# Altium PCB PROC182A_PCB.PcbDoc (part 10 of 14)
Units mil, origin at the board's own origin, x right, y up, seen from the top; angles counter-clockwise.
Board outline 3168.31 x 3700.79 mil, 8 copper layers (Top Layer, L2_GND1, L3_SIG1, L4_PWR1, L5_PWR2, L6_SIG2, L7_GND2, Bottom Layer), stack 58.1 mil thick; 580 components, 391 nets, 8314 pads, 4370 vias.
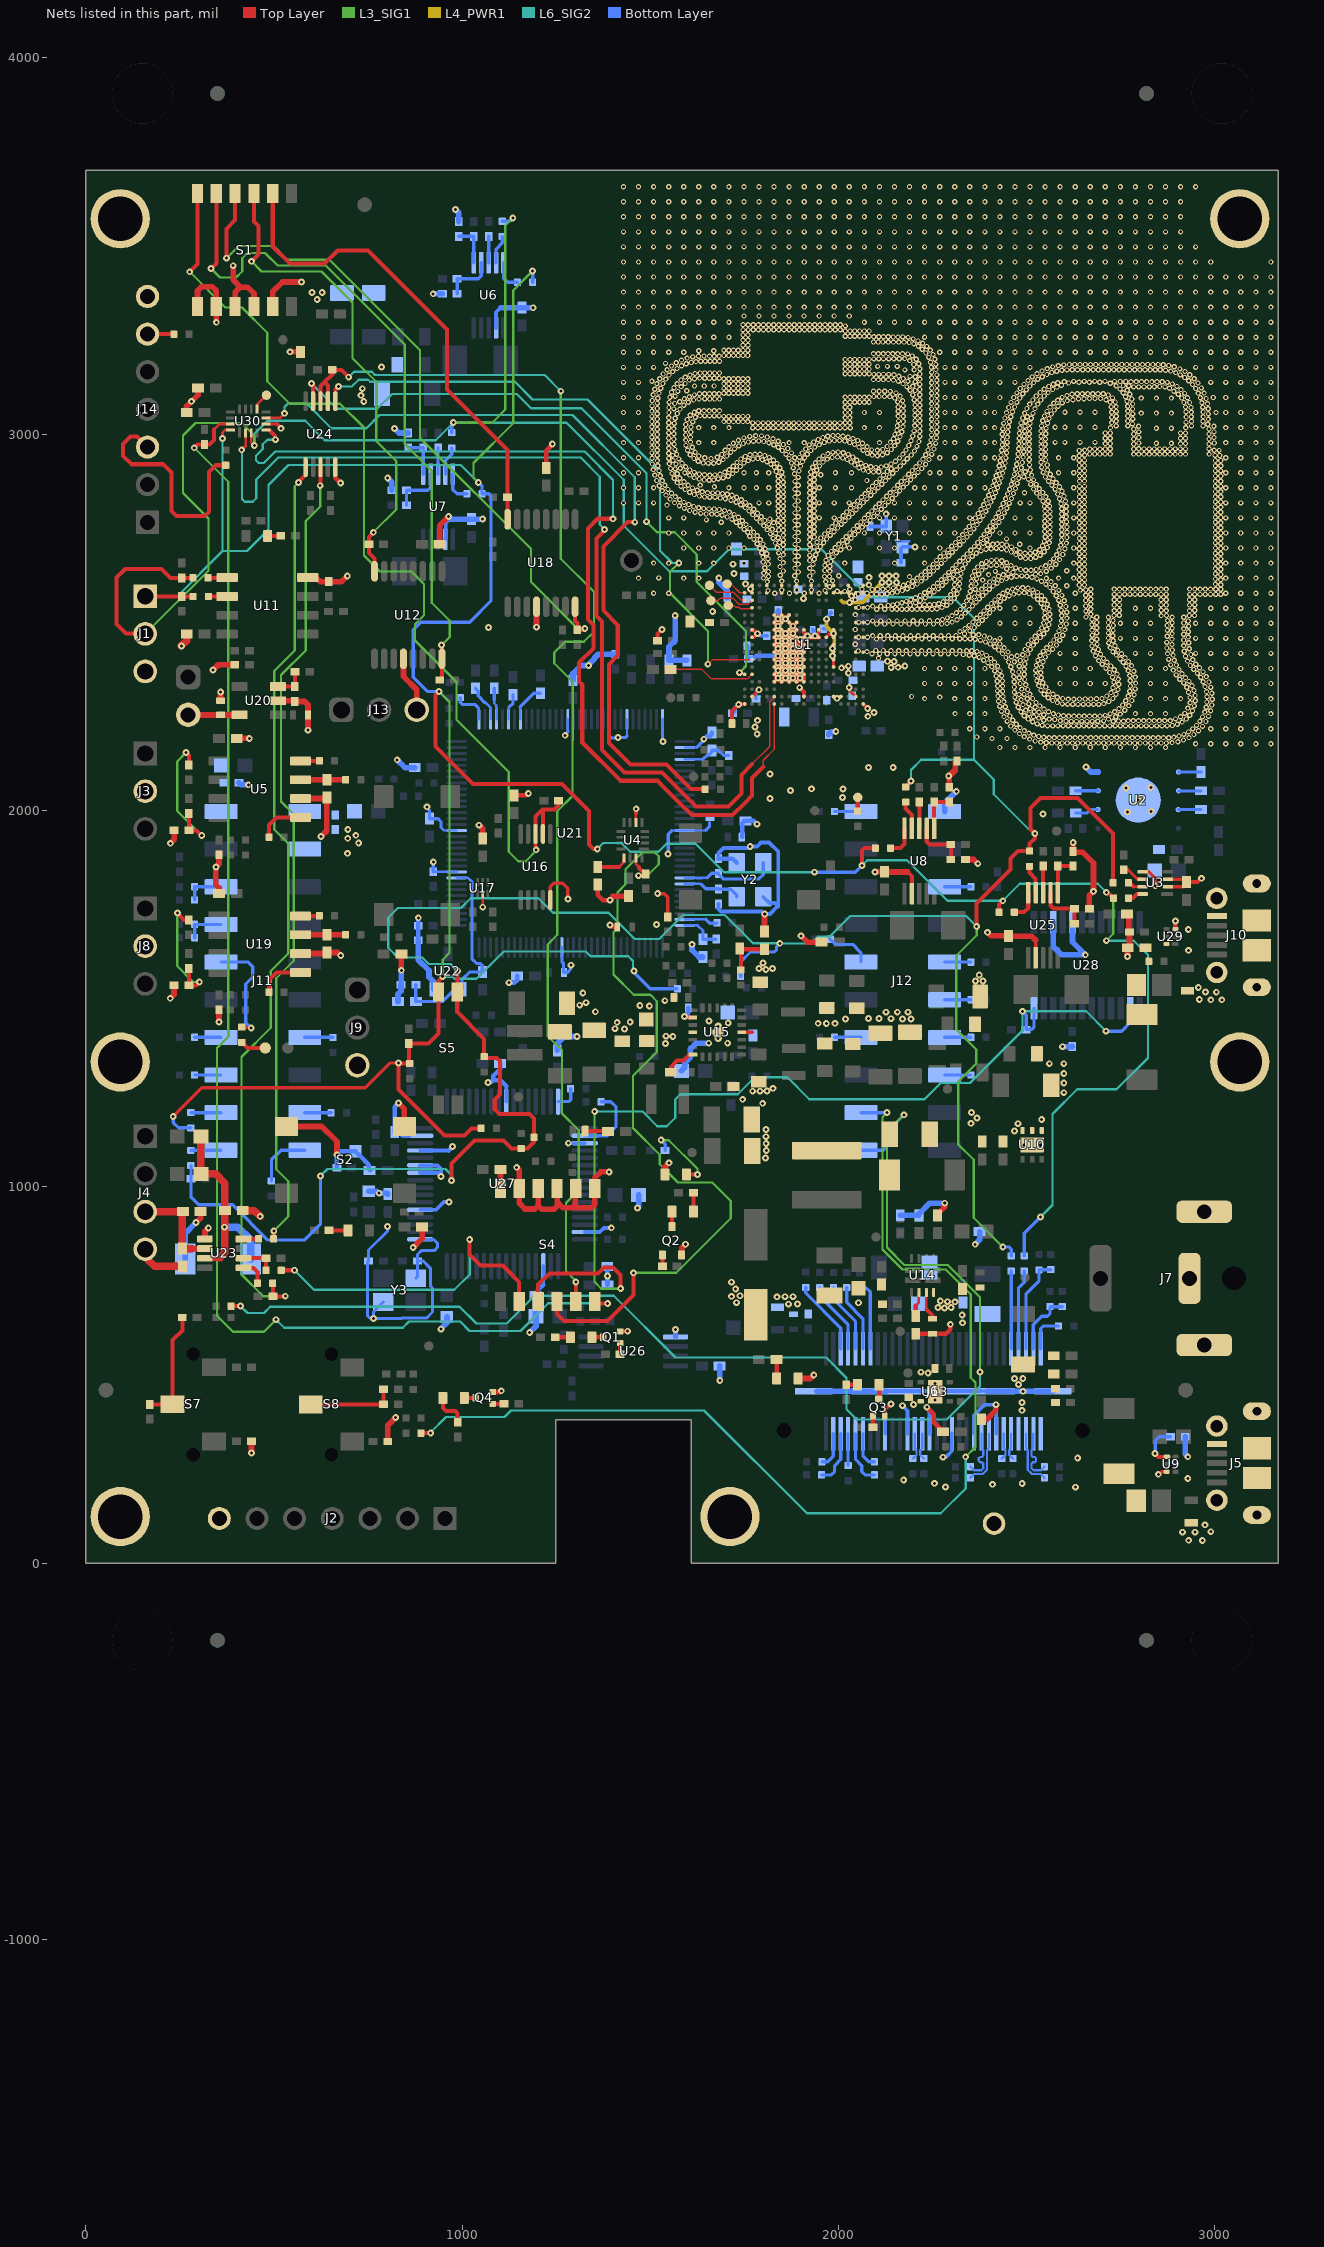
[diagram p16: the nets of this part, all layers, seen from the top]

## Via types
v1: diameter 13.77, hole 7, Top Layer to L2_GND1, tented both sides, 3444 vias
v2: diameter 18, hole 8, Top Layer to Bottom Layer, tented both sides, 911 vias
v3: diameter 13.77, hole 7, Top Layer to L2_GND1, tented top, 9 vias
v4: diameter 19.68, hole 7.87, Top Layer to Bottom Layer, 4 vias
v5: diameter 19.68, hole 7.87, Top Layer to Bottom Layer, tented both sides, 2 vias

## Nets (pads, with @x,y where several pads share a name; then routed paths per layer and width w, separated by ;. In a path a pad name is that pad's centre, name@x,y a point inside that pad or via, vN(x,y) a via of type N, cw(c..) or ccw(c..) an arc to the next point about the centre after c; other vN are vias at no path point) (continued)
GND: (continued)
  other v1: 2004.9,3290.63 1428.72,3297.48 1468.72,3297.48 1508.72,3297.48 1548.72,3297.48 1588.72,3297.48 1628.72,3297.48 1668.72,3297.48 1708.72,3297.48 2068.72,3297.48 2108.72,3297.48 2148.72,3297.48 2188.72,3297.48 2228.72,3297.48 2268.72,3297.48 2308.72,3297.48 2348.72,3297.48 2388.72,3297.48 2428.72,3297.48 2468.72,3297.48 2508.72,3297.48 2548.72,3297.48 2588.72,3297.48 2628.72,3297.48 2668.72,3297.48 2708.72,3297.48 2748.72,3297.48 2788.72,3297.48 2828.72,3297.48 2868.72,3297.48 2908.72,3297.48 2948.72,3297.48 2988.72,3297.48 3028.72,3297.48 3068.72,3297.48 3108.72,3297.48 3148.72,3297.48 1748.72,3314.06 1788.72,3314.06 1828.72,3314.06 1868.38,3314.06 1908.38,3314.06 1948.38,3314.06 1988.38,3314.06 2028.38,3314.06 1428.72,3337.48 1468.72,3337.48 1508.72,3337.48 1548.72,3337.48 1588.72,3337.48 1628.72,3337.48 1668.72,3337.48 1708.72,3337.48 1748.72,3337.48 1788.72,3337.48 1828.72,3337.48 1868.72,3337.48 1908.72,3337.48 1948.72,3337.48 1988.72,3337.48 2028.72,3337.48 2068.72,3337.48 2108.72,3337.48 2148.72,3337.48 2188.72,3337.48 2228.72,3337.48 2268.72,3337.48 2308.72,3337.48 2348.72,3337.48 2388.72,3337.48 2428.72,3337.48 2468.72,3337.48 2508.72,3337.48 2548.72,3337.48 2588.72,3337.48 2628.72,3337.48 2668.72,3337.48 2708.72,3337.48 2748.72,3337.48 2788.72,3337.48 2828.72,3337.48 2868.72,3337.48 2908.72,3337.48 2948.72,3337.48 2988.72,3337.48 3028.72,3337.48 3068.72,3337.48 3108.72,3337.48 3148.72,3337.48 1428.72,3377.48 1468.72,3377.48 1508.72,3377.48 1548.72,3377.48 1588.72,3377.48 1628.72,3377.48 1668.72,3377.48 1708.72,3377.48 1748.72,3377.48 1788.72,3377.48 1828.72,3377.48 1868.72,3377.48 1908.72,3377.48 1948.72,3377.48 1988.72,3377.48 2028.72,3377.48 2068.72,3377.48 2108.72,3377.48 2148.72,3377.48 2188.72,3377.48 2228.72,3377.48 2268.72,3377.48 2308.72,3377.48 2348.72,3377.48 2388.72,3377.48 2428.72,3377.48 2468.72,3377.48 2508.72,3377.48 2548.72,3377.48 2588.72,3377.48 2628.72,3377.48 2668.72,3377.48 2708.72,3377.48 2748.72,3377.48 2788.72,3377.48 2828.72,3377.48 2868.72,3377.48 2908.72,3377.48 2948.72,3377.48 2988.72,3377.48 3028.72,3377.48 3068.72,3377.48 3108.72,3377.48 3148.72,3377.48 1428.72,3417.48 1468.72,3417.48 1508.72,3417.48 1548.72,3417.48 1588.72,3417.48 1628.72,3417.48 1668.72,3417.48 1708.72,3417.48 1748.72,3417.48 1788.72,3417.48 1828.72,3417.48 1868.72,3417.48 1908.72,3417.48 1948.72,3417.48 1988.72,3417.48 2028.72,3417.48 2068.72,3417.48 2108.72,3417.48 2148.72,3417.48 2188.72,3417.48 2228.72,3417.48 2268.72,3417.48 2308.72,3417.48 2348.72,3417.48 2388.72,3417.48 2428.72,3417.48 2468.72,3417.48 2508.72,3417.48 2548.72,3417.48 2588.72,3417.48 2628.72,3417.48 2668.72,3417.48 2708.72,3417.48 2748.72,3417.48 2788.72,3417.48 2828.72,3417.48 2868.72,3417.48 2908.72,3417.48 2948.72,3417.48 2988.72,3417.48 3028.72,3417.48 3068.72,3417.48 3108.72,3417.48 3148.72,3417.48 1428.72,3457.48 1468.72,3457.48 1508.72,3457.48 1548.72,3457.48 1588.72,3457.48 1628.72,3457.48 1668.72,3457.48 1708.72,3457.48 1748.72,3457.48 1788.72,3457.48 1828.72,3457.48 1868.72,3457.48 1908.72,3457.48 1948.72,3457.48 1988.72,3457.48 2028.72,3457.48 2068.72,3457.48 2108.72,3457.48 2148.72,3457.48 2188.72,3457.48 2228.72,3457.48 2268.72,3457.48 2308.72,3457.48 2348.72,3457.48 2388.72,3457.48 2428.72,3457.48 2468.72,3457.48 2508.72,3457.48 2548.72,3457.48 2588.72,3457.48 2628.72,3457.48 2668.72,3457.48 2708.72,3457.48 2748.72,3457.48 2788.72,3457.48 2828.72,3457.48 2868.72,3457.48 2908.72,3457.48 2948.72,3457.48 2988.72,3457.48 3148.72,3457.48 1428.72,3497.48 1468.72,3497.48 1508.72,3497.48 1548.72,3497.48 1588.72,3497.48 1628.72,3497.48 1668.72,3497.48 1708.72,3497.48 1748.72,3497.48 1788.72,3497.48 1828.72,3497.48 1868.72,3497.48 1908.72,3497.48 1948.72,3497.48 1988.72,3497.48 2028.72,3497.48 2068.72,3497.48 2108.72,3497.48 2148.72,3497.48 2188.72,3497.48 2228.72,3497.48 2268.72,3497.48 2308.72,3497.48 2348.72,3497.48 2388.72,3497.48 2428.72,3497.48 2468.72,3497.48 2508.72,3497.48 2548.72,3497.48 2588.72,3497.48 2628.72,3497.48 2668.72,3497.48 2708.72,3497.48 2748.72,3497.48 2788.72,3497.48 2828.72,3497.48 2868.72,3497.48 2908.72,3497.48 2948.72,3497.48 1428.72,3537.48 1468.72,3537.48 1508.72,3537.48 1548.72,3537.48 1588.72,3537.48 1628.72,3537.48 1668.72,3537.48 1708.72,3537.48 1748.72,3537.48 1788.72,3537.48 1828.72,3537.48 1868.72,3537.48 1908.72,3537.48 1948.72,3537.48 1988.72,3537.48 2028.72,3537.48 2068.72,3537.48 2108.72,3537.48 2148.72,3537.48 2188.72,3537.48 2228.72,3537.48 2268.72,3537.48 2308.72,3537.48 2348.72,3537.48 2388.72,3537.48 2428.72,3537.48 2468.72,3537.48 2508.72,3537.48 2548.72,3537.48 2588.72,3537.48 2628.72,3537.48 2668.72,3537.48 2708.72,3537.48 2748.72,3537.48 2788.72,3537.48 2828.72,3537.48 2868.72,3537.48 2908.72,3537.48 1428.72,3577.48 1468.72,3577.48 1508.72,3577.48 1548.72,3577.48 1588.72,3577.48 1628.72,3577.48 1668.72,3577.48 1708.72,3577.48 1748.72,3577.48 1788.72,3577.48 1828.72,3577.48 1868.72,3577.48 1908.72,3577.48 1948.72,3577.48 1988.72,3577.48 2028.72,3577.48 2068.72,3577.48 2108.72,3577.48 2148.72,3577.48 2188.72,3577.48 2228.72,3577.48 2268.72,3577.48 2308.72,3577.48 2348.72,3577.48 2388.72,3577.48 2428.72,3577.48 2468.72,3577.48 2508.72,3577.48 2548.72,3577.48 2588.72,3577.48 2628.72,3577.48 2668.72,3577.48 2708.72,3577.48 2748.72,3577.48 2788.72,3577.48 2828.72,3577.48 2868.72,3577.48 2908.72,3577.48 1428.72,3617.48 1468.72,3617.48 1508.72,3617.48 1548.72,3617.48 1588.72,3617.48 1628.72,3617.48 1668.72,3617.48 1708.72,3617.48 1748.72,3617.48 1788.72,3617.48 1828.72,3617.48 1868.72,3617.48 1908.72,3617.48 1948.72,3617.48 1988.72,3617.48 2028.72,3617.48 2068.72,3617.48 2108.72,3617.48 2148.72,3617.48 2188.72,3617.48 2228.72,3617.48 2268.72,3617.48 2308.72,3617.48 2348.72,3617.48 2388.72,3617.48 2428.72,3617.48 2468.72,3617.48 2508.72,3617.48 2548.72,3617.48 2588.72,3617.48 2628.72,3617.48 2668.72,3617.48 2708.72,3617.48 2748.72,3617.48 2788.72,3617.48 2828.72,3617.48 2868.72,3617.48 2908.72,3617.48 1428.72,3657.48 1468.72,3657.48 1508.72,3657.48 1548.72,3657.48 1588.72,3657.48 1628.72,3657.48 1668.72,3657.48 1708.72,3657.48 1748.72,3657.48 1788.72,3657.48 1828.72,3657.48 1868.72,3657.48 1908.72,3657.48 1948.72,3657.48 1988.72,3657.48 2028.72,3657.48 2068.72,3657.48 2108.72,3657.48 2148.72,3657.48 2188.72,3657.48 2228.72,3657.48 2268.72,3657.48 2308.72,3657.48 2348.72,3657.48 2388.72,3657.48 2428.72,3657.48 2468.72,3657.48 2508.72,3657.48 2548.72,3657.48 2588.72,3657.48 2628.72,3657.48 2668.72,3657.48 2708.72,3657.48 2748.72,3657.48 2788.72,3657.48 2828.72,3657.48 2868.72,3657.48 2908.72,3657.48 2948.72,3657.48
  other v2: 2930.14,61.29 2966.32,60.76 2913.5,82.95 2946.78,82.95 2989.09,84.24 2973.52,102.49 2284.41,202.64 2629.78,202.51 2408.71,210.01 2488.02,212.24 2254.92,212.6 2173.08,221.6 2927.8,225.73 2635.36,279.7 2487.66,406.67 2199.28,421.83 2487.66,427.69 2478.38,475.32 2467.41,491.46 2489.5,491.46 2238.1,505.9 2218.86,507.95 2329.22,639.12 2328.48,659.72 2281.72,678.28 2264.28,679.81 2299.45,680.1 1867.11,688.69 1890.71,689.21 1729.1,692.46 2052.8,692.41 2309.31,694.85 2289.77,695.33 2270.3,696.75 1836.28,708.23 1857.83,708.52 1879.37,708.52 1715.67,709.58 1738.51,711 1726.65,729.18 1715.43,746.93 1390.72,1039.43 1805.9,1077.2 1808.23,1096.81 974.7,1107.54 1807.94,1115.66 1807.34,1133.65 2467.62,1148.59 1807.04,1152.62 2476.71,1168.11 2352.07,1169.26 2539.87,1179.47 2367.71,1182.91 2353.19,1198.09 1798.48,1222.21 1745.26,1232.95 2598.37,1250.48 1772.04,1254.37 1791.58,1254.37 1809.93,1254.77 1825.57,1262.16 2598.37,1276.15 2598.37,1301.81 2560.02,1327.48 2598.37,1327.48 1540.24,1381.5 1705.5,1382.07 1559.8,1400.05 1541.63,1400.56 1431.32,1419.47 1405.91,1420.36 1945.86,1434.73 1967.57,1434.42 1990.66,1434.67 1706.91,1435.82 1411.86,1437.35 1446.64,1438.58 1655.61,1441.09 2018.24,1446.23 2170.18,1446.14 2192.27,1445.88 2139.59,1447.05 2079.52,1447.85 2107.85,1447.85 2125.82,1464.45 2156.25,1464.45 2184.79,1464.45 1353.91,1465.5 1497.32,1481.02 1472.05,1481.74 1312.4,1483.01 1329.15,1489.61 1538.6,1494.91 2989.13,1497.28 2958.54,1498.19 3018.33,1497.32 224.58,1501.17 1320.57,1515.23 2975.2,1517.88 3003.74,1517.55 2955.88,1530.2 2364.07,1547.42 2383.59,1547.42 2373.83,1562.93 1806.87,1577.89 1824.73,1580.18 1788.87,1580.62 1799.26,1595.32 2929.95,1628.72 2929.12,1684 1516.66,1697.15 695.14,1886.32 224.75,1912.88 725.14,1913.47 696.14,1926.32 717.5,1934.3 696.27,1949.79 2543.55,1990.67 2767.72,1996.06 2830.71,1998.03 2796.23,2027.59 1817.85,2031.89 2010.49,2034.35 1872.45,2053.61 2011.6,2057.18 1928.45,2057.65 2763.78,2060.04 2829.72,2061.02 1817.85,2097.47 2079.59,2114.28 2145.16,2114.28 1784.04,2203.37 1778.13,2221.64 1785.02,2239.9 2077.88,2250.39 2094.12,2260.51 1996.01,2298.17 2026.08,2365.54 2008.46,2379.38 2140.02,2380.38 2158.45,2380.58 2026.08,2383.59 2176.13,2384.41 2147.86,2396.26 2129.84,2396.68 1898.23,2454.32 1070.01,2486.68 1665.81,2528.52 1907.06,2562.86 2034.62,2570.67 1766.28,2588.28 2080.48,2599.8 1753.06,2602.44 2134.19,2605.63 2154.32,2605.63 2080.87,2619.66 2115.84,2623.61 2133.82,2623.61 2153.03,2623.61 1722.44,2629.92 1719.99,2654.51 677.27,2870.41 738.81,3086.68 731.44,3103.1 734.74,3120.8 785.86,3178.55 346.89,3297.26 615.09,3357.47 601.3,3376.39 628.2,3376.39
  other v3: 1688.23,2765.94 1648.86,2772.16 1544.19,2811.53 1670.21,2860.34 1632.73,2864.66 2762.29,3099.2 2592.19,3130.16 1504.08,3140.67 1540.2,3187.97
  other v4: 2256.79,434.09 2256.79,477.4 2492.67,1111.65 2535.97,1111.65
  other v5: 1680.35,1394.98 1680.35,1426.56
GPADC1: TP11.1 U1.T4 | length 68.3
  Top Layer w4: TP11.1@1707.08,2545.15 1708.53,2543.7 1723.27,2543.7 1725.16,2541.81 1727.14,2539.83 1736.2,2539.83 1740.03,2536 1765.64,2536 1768.7,2539.06 U1.T4@1770.28,2539.06
GPADC2: TP12.1 U1.T3 | length 123.8
  Top Layer w4: TP12.1@1660.83,2557.74 1679.14,2557.74 1686.05,2564.65 1719.46,2564.65 1736.28,2547.83 1759.42,2547.83 U1.T3@1770.28,2558.75 U1.T3@1770.28,2558.75
GPADC3: TP5.1 U1.U2 | length 56.3
  Top Layer w4: TP5.1@1703.94,2601.77 1714.1,2601.77 1737.43,2578.43 U1.U2@1750.59,2578.43
GPADC4: TP6.1 U1.U3 | length 110.2
  Top Layer w4: TP6.1@1657,2598.24 1675.51,2579.73 1720.99,2579.73 1741.63,2559.08 1741.63,2558.75 U1.U3@1750.59,2558.75
HARDWARE_TRIGGER: J15.2 R254.1 | length 68.5
  Top Layer w10.8: R254.1@414.56,1384.37 429.5,1369.43 J15.2@476.88,1369.43
HOST_CLK_REQ: TP4.1 U30.9 | length 47.5
  Top Layer w7: U30.9@455.49,3066.34 455.49,3078.91 TP4.1@480.15,3103.58
HOST_CLK_REQ_SPIB_MISO: R270.2 U30.7 | length 2199.3
  Top Layer w7: U30.7@479.37,3042.98 515.53,3042.98 v2@528.05,3055.49
  Top Layer w10.8: v2(1458.91,2766.17) 1439.56,2766.17 1375.46,2702.08 1375.46,2530.98 1413.41,2493.03 1413.41,2411.79 1390.21,2388.59 1390.21,2179.27 1446.75,2122.72 1542.66,2122.72 1608.63,2056.76 R270.2@1645.51,2056.76
  L6_SIG2 w6: v2(528.37,3055.49) 528.37,3072.44 538.54,3082.6 585.98,3082.6 652.63,3015.96 745.97,3015.96 780.65,3050.64 1293.48,3050.64 1458.91,2885.22 v2(1458.91,2766.17)
HOSTIRQ_FTDI_IN: R216.1 U27.32 | length 64.7
  Bottom Layer w8.7: U27.32@1255.02,1226.8 1282.95,1226.8 1288.3,1232.15 R216.1@1288.3,1261.32
HOSTIRQ_FTDI_OUT: R217.1 U27.34 | length 191
  Bottom Layer w8.7: U27.34@1325.89,1136.25 1384.95,1136.25 1408.77,1160.07 1408.77,1212.89 1395.24,1226.42 1369.11,1226.42 R217.1@1369.01,1226.32
I2C_SCL: J1.1 R25.2 R55.2 R60.1 R89.1 R96.2 R97.1 R108.2 R109.2 R137.2 R159.2 R164.1 R199.1 R224.1 S5.2 U30.16 | length 9572.2
  Top Layer w7: v2(363.51,2988.52) 363.51,3004.42 370.31,3011.22 U30.16@384.62,3011.22
  Top Layer w8.7: v2(232.5,1187.58) 308.85,1263.93 742.83,1263.93 808.09,1329.2 v2(830.69,1329.2)
  Top Layer w10.8: J1.1@158.07,2569.5 158.78,2568.79 R97.1@254.77,2568.79 R159.2@285.26,2568.79 ; R199.1@860.53,1327.87 R199.1@859.86,1328.54 ; v2(938.48,2316.6) 928.92,2307.04 928.92,2170.56 1028.72,2070.75 1264.77,2070.75 1337.1,1998.43 1337.1,1909.31 1348.71,1897.69 v2(1359.02,1897.69) ; v2(948.29,1558.77) 937.08,1547.56 S5.2@937.08,1518.36 937.08,1407.62 910.54,1381.09 R164.1@858.69,1381.09 858.69,1329.71 R199.1@859.86,1328.54 ; R96.2@1050.6,1155.7 1025.05,1155.7 1006.37,1137.02 953.19,1137.02 830.69,1259.52 v2(830.69,1329.2) 831.36,1328.54 R199.1@859.86,1328.54 ; v2(2062.31,1854.08) 2062.13,1854.26 2062.13,1894.02 2068.45,1900.35 R109.2@2097.68,1900.35 ; R137.2@2426.53,1730.11 2426.53,1750.41 v2(2436.39,1760.28) ; v2(2711.47,1782.77) 2712.85,1781.39 2716.26,1781.39 2725.86,1771.78 2726.36,1771.78 2730.1,1768.04 R55.2@2730.1,1767.55
  L3_SIG1 w6: v2(938.48,2316.6) 966.35,2288.73 966.35,1622.03 948.29,1603.97 v2(948.29,1558.77) ; v2(1043.12,2871.78) 1030.28,2884.62 1030.28,2923.5 1135.53,3028.75 1135.53,3381.91 v2(1187.17,3433.55) ; v2(2711.38,1654.24) 2729.65,1672.51 2729.65,1764.59 v2(2711.47,1782.77)
  L6_SIG2 w6: J1.1@158.07,2569.5 243.71,2569.5 363.51,2689.3 ; v2(363.51,2988.52) 363.51,2689.3 ; v2(948.29,1558.77) 974.25,1558.77 980.05,1552.96 1038.26,1552.96 1110.91,1625.61 1328.48,1625.61 1341.13,1612.96 1441.3,1612.96 1453.95,1600.31 1453.95,1582.22 1454.17,1582.01 1454.17,1576.18 v2(1456.46,1573.88) ; v2(1043.12,2871.78) 996.65,2918.26 538.94,2918.26 485.86,2865.17 485.86,2746.67 428.49,2689.3 363.51,2689.3 ; v2(1359.02,1897.69) 1375.12,1913.8 1423.52,1913.8 1446.68,1890.64 1521.97,1890.64 1543.01,1911.68 1620.14,1911.68 1695.54,1836.28 v2(1936.42,1836.28) ; v2(2062.31,1854.08) 2076.06,1867.83 2181.8,1867.83 2289.36,1760.28 v2(2436.39,1760.28) 2481.61,1805.49 2688.75,1805.49 v2(2711.47,1782.77) ; v2(2536.34,920.08) 2568.55,952.28 2568.55,1193.69 2634.25,1259.39 2738.8,1259.39 2822.06,1342.65 2822.06,1616.65 2784.47,1654.24 v2(2711.38,1654.24)
  Bottom Layer w8.7: v2(232.5,1187.58) 232.5,1171.05 246.45,1157.1 R224.1@279.56,1157.1 ; v2(938.48,2316.6) 907.72,2316.6 869.93,2354.39 869.93,2480.45 889.98,2500.5 1020.38,2500.5 1076.73,2556.85 1076.73,2836.52 1071.63,2841.61 R108.2@1052.99,2841.61 1052.99,2861.91 v2(1043.12,2871.78) ; v2(1187.17,3433.55) 1187.28,3433.44 1187.28,3403.51 R25.2@1187.39,3403.4 ; v2(1456.46,1573.88) 1456.46,1571.36 1459.38,1568.44 1459.38,1567.07 1499.48,1526.97 R89.1@1571.15,1526.97 ; v2(1936.42,1836.28) 2044.51,1836.28 v2(2062.31,1854.08) ; R60.1@2493.18,817.03 2493.18,876.92 v2(2536.34,920.08)
I2C_SCL_SPIB_CLK: U1.N16 U30.2 | length 2720.3
  Top Layer w4: 1770.34,2123.54 1817.92,2171.11 1817.92,2290.47 1829.33,2301.89 U1.N16@1829.33,2302.84
  Top Layer w7: v2(414.51,2958.37) 415.34,2958.37 424.94,2967.97 424.94,2991.59 424.43,2992.11 424.43,3002.91 U30.2@423.99,3003.35
  Top Layer w10.8: v2(1378.46,2746.54) 1378.46,2744.63 1356.44,2722.61 1356.44,2516.54 1371.19,2501.79 1371.19,2161.52 1431.85,2100.86 1531.2,2100.86 1613.27,2018.79 1620.75,2011.31 1708.01,2011.31 1715.5,2018.79 1741.88,2045.18 1741.88,2095.08 1770.34,2123.54
  L6_SIG2 w6: v2(414.51,2958.37) 415.47,2957.41 415.47,2827.5 422.61,2820.36 443.69,2820.36 453.3,2829.96 453.3,2879.6 511.43,2937.73 1315.15,2937.73 1365.95,2886.92 1365.95,2760 1378.46,2747.5 v2(1378.46,2746.54)
I2C_SDA: J1.2 R29.2 R56.2 R59.1 R90.1 R98.1 R100.2 R102.2 R110.2 R111.2 R139.2 R160.2 R166.1 R197.1 R238.1 S5.1 U30.3 | length 11184.4
  Top Layer w7: U30.3@439.74,3003.35 439.74,2977.98 447.79,2969.93 v2(447.79,2969.77)
  Top Layer w10.8: J1.2@158.07,2469.5 157.57,2470 107.1,2470 81.89,2495.21 81.89,2619.19 105.04,2642.34 200.72,2642.34 224.73,2618.33 R98.1@254.77,2618.33 R160.2@284.77,2618.33 ; v2(971.74,1017.32) 971.74,1061.84 1033.26,1123.36 1109.38,1123.36 1130.7,1102.04 1174.15,1102.04 1190.95,1118.84 1190.95,1182.32 1179.53,1193.74 1098.7,1193.74 1086.75,1205.69 1086.75,1232.31 1100.23,1245.8 1100.23,1334.11 1091.47,1342.88 1061.61,1342.88 R197.1@1058.48,1346.02 1058.48,1392.92 987.08,1464.32 S5.1@987.08,1518.36 987.55,1518.83 987.55,1573.01 v2(988.02,1573.48) ; R111.2@2178.41,2062.59 2178.9,2062.59 2182.85,2066.54 2182.85,2068.83 v2(2192.81,2078.79) ; v2(2366.94,1691.84) 2366.94,1752.67 2457.26,1842.99 2457.26,1872.23 2477.38,1892.35 R139.2@2507.26,1892.35 2507.26,1912.22 2521.42,1926.39 v2(2521.42,1939.35) 2510.42,1950.36 2510.42,2006.87 2536.94,2033.39 2635.26,2033.39 2727.71,1940.95 2727.71,1940.71 2729.7,1938.72 R56.2@2729.7,1807.94
  L3_SIG1 w6: J1.2@158.07,2469.5 325.91,2637.35 325.91,2776.12 258.27,2843.76 258.27,2996.46 291.34,3029.53 414.8,3029.53 447.79,2996.54 v2(447.79,2969.77) ; v2(976.44,3030.64) 1079.85,3030.64 1114.77,3065.56 1114.77,3554.37 v2(1134.77,3574.37) ; v2(2366.94,1691.84) 2366.94,1668.6 2312.88,1614.53 2312.88,1418.63 2366.17,1365.33 2366.17,1328.1 2318.31,1280.24 2318.31,1112.68 2358.93,1072.06 2358.93,918.17 v2(2436.34,840.76)
  L6_SIG2 w6: v2(447.79,2969.77) 447.79,3000.4 482.89,3035.49 583,3035.49 634.6,2983.9 929.7,2983.9 v2(976.44,3030.64) 1277.6,3030.64 1429.06,2879.18 1429.06,2756.6 1550.13,2635.52 1650.74,2635.52 1709.31,2694.09 1954.84,2694.09 2082.28,2566.64 2304.18,2566.64 2359.91,2510.91 2359.91,2134.78 ; v2(623.98,1029.47) 642.33,1047.82 955.93,1047.82 971.74,1032.01 v2(971.74,1017.32) ; v2(988.02,1573.48) 968.92,1592.58 911.57,1592.58 894.24,1609.9 829.52,1609.9 803.96,1635.46 803.96,1716.16 829.21,1741.42 996.99,1741.42 1022.63,1767.06 1202.92,1767.06 1241.5,1728.47 1388.85,1728.47 1458.33,1658.99 1523.97,1658.99 1587.69,1722.71 1697.45,1722.71 1772.84,1647.32 v2(1843.91,1647.32) ; v2@1843.91,1647.13 1927.53,1647.13 1945.37,1664.97 1976.08,1664.97 2030.9,1719.78 2339,1719.78 v2(2366.94,1691.84) ; v2(2192.81,2078.79) 2192.81,2107.96 2219.63,2134.78 2359.91,2134.78 ; v2(2521.42,1939.35) 2509.17,1951.6 2503.98,1951.6 2412.16,2043.42 2412.16,2082.53 2359.91,2134.78
  Bottom Layer w8.7: R238.1@279.56,1057.1 R166.1@279.56,1022.1 279.56,973.74 300.6,952.7 390.37,952.7 484.08,858.99 581.05,858.99 623.98,901.92 v2(623.98,1029.47) ; R110.2@972.26,3003.85 972.26,3026.46 v2(976.44,3030.64) ; R29.2@1106.66,3565.64 1126.05,3565.64 v2(1134.77,3574.37) ; R90.1@1740.13,1560.01 1740.13,1598.18 1766.15,1624.2 1828.79,1624.2 1835.39,1630.81 1835.39,1638.81 v2(1843.91,1647.32) ; v2(2436.34,840.76) 2451.86,840.76 2458.51,834.11 R59.1@2458.51,817.03
I2C_SDA_SPIB_MOSI: U1.N17 U30.5 | length 2720.4
  Top Layer w4: 1799.93,2115.55 1799.93,2133.6 1829.59,2163.25 U1.N17@1829.59,2282.9
  Top Layer w7: U30.5@479.11,3011.22 U30.5@487.96,3011.22
  Top Layer w10.8: U30.5@487.96,3011.22 496.86,3002.32 496.86,3001.77 503.04,2995.59 503.04,2986.77 v2(504.42,2985.39) ; v2(1400.59,2775.24) 1359.53,2775.24 1333.88,2749.6 1333.88,2507.59 1348.63,2492.85 1348.63,2430.31 1311.06,2392.75 1311.06,2342.93 1319.11,2334.88 1319.11,2181.23 1421.08,2079.26 1518.91,2079.26 1528.36,2069.82 1579.38,2018.79 1610.53,1987.65 1718.51,1987.65 1749.65,2018.79 1770.26,2039.4 1770.26,2085.88 1799.93,2115.55
  L6_SIG2 w6: v2(504.42,2985.39) 482.96,2985.39 470.43,2972.86 470.43,2960.71 452.07,2942.35 452.07,2930.97 459.79,2923.25 473.27,2923.25 503.67,2953.64 1325.47,2953.64 1400.59,2878.53 v2(1400.59,2775.24)
JTAG_TDO: R93.2 U1.T13 | length 231.1
  Top Layer w4: R93.2@1554,2374.99 1637.11,2374.99 1661.57,2350.53 1758.91,2350.53 U1.T13@1770.28,2361.9
LIN_BUS: C132.1 J4.3 R21.1 U23.6 | length 258.7
  Top Layer w15: 281.35,836.32 U23.6@316.77,836.32
  Top Layer w20: J4.3@158.07,934.5 R21.1@258.07,934.5 256.77,933.21 C132.1@256.77,836.32 281.35,836.32
LIN_PHY_EN: R17.1 R88.2 U23.2 | length 92
  Top Layer w10.8: U23.2@419.13,810.73 R17.1@479.13,810.73 R88.2@479.13,778.73
LIN_PHY_EN_CTRL: R88.1 S4.2 | length 884
  Top Layer w10.8: R88.1@520.19,779.02 520.47,778.74 v2(554.35,778.75) ; v2(1020.01,860.48) 1020.01,820.44 1049.37,791.09 1107.92,791.09 1151.62,747.39 S4.2@1151.62,696.54
  L6_SIG2 w6: v2(554.35,778.75) 606.4,726.71 978.95,726.71 1020.01,767.77 v2(1020.01,860.48)
LIN_PHY_RX: R18.1 R22.1 U24.1 | length 2454.8
  Top Layer w10.8: R18.1@497.04,743.84 R22.1@497.04,709.34 529.91,709.34 v2(530.38,709.81) ; v2(565.44,2871.3) 565.44,2872.76 583.97,2891.29 583.97,2911.91 U24.1@584.32,2912.26
  L3_SIG1 w6: v2(530.38,709.81) 471.6,709.81 413.71,767.7 413.71,1345.48 491.49,1423.26 491.49,1573.93 538.09,1620.53 538.09,1912.71 500.87,1949.93 500.87,2370.63 555.64,2425.4 555.64,2861.51 v2(565.44,2871.3)
LIN_PHY_RX_UARTB_TX: U1.U13 U24.9 | length 1759.4
  Top Layer w4: v2(1737.01,2366.36) 1740.8,2366.36 1744.14,2363.02 1749.48,2363.02 U1.U13@1750.59,2361.9
  Top Layer w10.8: v2(599.79,3134.61) 604.01,3130.39 U24.9@604.01,3087.46
  L3_SIG1 w6: v2(1489.78,2767.46) 1517.96,2739.28 1564.67,2739.28 1623.51,2680.44 1623.51,2660.18 1623.51,2607.25 1754.08,2476.68 1754.08,2383.43 v2(1737.01,2366.36)
  L6_SIG2 w6: v2(599.79,3134.61) 666.84,3067.55 774.81,3067.55 814.17,3106.92 1144.78,3106.92 1182.67,3069.03 1316.86,3069.03 1489.78,2896.11 v2(1489.78,2767.46)
LIN_PHY_TX: R19.1 U24.3 | length 2155.7
  Top Layer w10.8: R19.1@499.49,861.92 499.49,882.7 v2(499.67,882.88) ; v2(623.03,2863.19) 623.5,2863.66 623.5,2912.07 U24.3@623.69,2912.26
  L3_SIG1 w6: v2(499.67,882.88) 538.03,921.25 538.03,1015.49 506.37,1047.15 506.37,1554.57 552.5,1600.69 552.5,1990.34 519.08,2023.75 519.08,2360.09 584.43,2425.43 584.43,2769.33 623.03,2807.94 v2(623.03,2863.19)
LIN_PHY_TX_UARTB_RX: U1.T11 U24.6 | length 1721.8
  Top Layer w4: v2(1652.72,2388.94) 1665.09,2401.27 U1.T11@1770.28,2401.27
  Top Layer w10.8: U24.6@663.06,3087.46 663.06,3118.19 v2(671.23,3126.35)
  L3_SIG1 w6: v2(1575.57,2657.88) 1552.03,2634.34 1552.03,2577.69 1653.07,2476.65 1653.07,2389.29 v2(1652.72,2388.94)
  L6_SIG2 w6: v2(671.23,3126.35) 706.79,3126.35 725.28,3144.85 750.22,3144.85 756.15,3138.92 1140.24,3138.92 1187.22,3091.94 1333.37,3091.94 1525.65,2899.66 1525.65,2690.58 1556.05,2660.18 1558.34,2657.88 v2(1575.57,2657.88)
LIN_VDD: C123.1 D8.2 R31.2 R32.2 U23.7 | length 552.5
  Top Layer w15: U23.7@316.77,810.73 355.67,810.73 356.73,811.79
  Top Layer w20: R31.2@306.06,1134.5 R32.2@306.06,1034.5 345.85,1034.5 369.9,1010.45 C123.1@369.9,937.13 369.9,824.97 356.73,811.79
  Bottom Layer w20: v2(369.03,893.27) 404.26,893.27 437.98,859.56 D8.2@437.98,808.26
LVDS_VALID: R257.2 TP3.1 | length 36.5
  Top Layer w10.8: R257.2@2051.07,1998.65 TP3.1@2051.07,2035.16
MCU_3V3: C119.1 J11.1 R154.1
MCU_5V: C120.1 J11.2 R155.1
MCU_SOP0: J12.19 R235.2 | length 3360.2
  Top Layer w10.8: R235.2@386.3,683.31 386.42,683.19 411.18,683.19 v2(411.42,683.43)
  L3_SIG1 w6: v2(2173.96,1191.67) 2128.66,1146.37 2128.66,838.95 2174.68,792.93 2289.83,792.93 2375.55,707.21 v2(2375.55,508.76)
  L6_SIG2 w6: v2(411.42,683.43) 429.67,665.18 473.71,665.18 490.51,681.98 993.29,681.98 1037.99,637.28 1118.7,637.28 1192.19,710.76 1402.67,710.76 1566.57,546.87 1967.05,546.87 2021.2,492.73 2021.2,409.77 2048.65,382.32 2287.42,382.32 2375.55,470.45 v2(2375.55,508.76)
  Bottom Layer w8.7: J12.19@2059.56,1097.45 2119.12,1097.45 2144.28,1122.61 2144.28,1161.99 v2(2173.96,1191.67)
MCU_SOP1: J12.17 R244.2 | length 2866.7
  Top Layer w10.8: R244.2@891.14,346.19 891.3,346.35 916.34,346.35 v2(916.5,346.51)
  L3_SIG1 w6: v2(2129.09,1197.52) 2116.66,1185.1 2116.66,833.98 2169.71,780.93 2284.54,780.93 2351.42,714.06 2351.42,492.91 2363.73,480.59 2363.73,309.14 v2(2337.76,283.17)
  L6_SIG2 w6: v2(916.5,346.51) 916.5,348.18 957.38,389.06 1112.44,389.06 1129.76,406.38 1642.83,406.38 1916.2,133.02 2271.8,133.02 2337.76,198.98 v2(2337.76,283.17)
  Bottom Layer w8.7: J12.17@2059.56,1197.45 2059.63,1197.52 v2(2129.09,1197.52)
MUX_CTRL_FTDI_DCA_LP_UARTA: R95.1 S1.6 U16.7 U16.8 | length 2619.1
  Top Layer w8: 1214.07,2002.98 1214.65,2002.4
  Top Layer w10.8: v2(276.25,3431.28) 296.89,3451.92 S1.6@296.89,3639.18 ; v2(1196.88,1895.79) 1196.88,1897.74 1194.68,1899.94 1194.68,1916.18 1194.77,1916.27 1194.77,1937.66 U16.8@1194.96,1937.85 1194.96,1983.88 1214.07,2002.98 ; U16.7@1214.65,1937.85 1214.65,2002.4 1245.08,2002.4 1256.51,2013.83 R95.1@1256.51,2026.17
  L3_SIG1 w6: v2(276.25,3431.28) 370.92,3336.62 415.35,3336.62 482.28,3269.69 482.28,3140.75 542.32,3080.71 675.81,3080.71 739.02,3017.49 739.02,2677.32 781.5,2634.84 865.59,2634.84 898.92,2601.52 898.92,2519.11 874.81,2495 874.81,2451.54 985.01,2341.34 985.01,2241.48 1124.01,2102.48 1124.01,1890.75 1149.2,1865.56 1168.77,1865.56 1196.88,1893.67 v2(1196.88,1895.79)
MUX_CTRL_FTDI_DCA_RS232: R7.1 S1.3 U12.16 | length 1305.3
  Top Layer w10.8: v2(440.39,3459.09) 459.22,3477.92 459.22,3552.37 446.89,3564.71 S1.3@446.89,3639.18 ; v2(764.13,2739.16) 752.22,2727.24 752.22,2684.8 767.33,2669.7 U12.16@767.33,2635.52
  L3_SIG1 w6: v2(440.39,3459.09) 467.12,3432.35 626.17,3432.35 708.66,3349.86 708.66,3201.77 771.54,3138.89 771.54,2981.62 824.8,2928.36 824.8,2799.83 v2(764.13,2739.16)
MUX_CTRL_FTDI_DCA_SPIA: R12.2 S4.3 U28.14 U28.24 | length 2723.4
  Top Layer w10.8: S4.3@1202.05,696.11 1202.05,740.63 1231.65,770.23 1361.2,770.23 1376.93,785.96 1401.23,785.96 1421.24,765.95 v2(1421.24,729.92)
  L3_SIG1 w6: v2@1351.9,1199.97 1351.9,747.96 1369.94,729.92 v2(1421.24,729.92)
  L6_SIG2 w6: v2(1352.16,1200.23) 1479.62,1200.23 1518.57,1161.28 1543.42,1161.28 1566.05,1183.91 1566.05,1232.5 1579.77,1246.22 1732.44,1246.22 1777.49,1291.28 1864.37,1291.28 1922.38,1233.27 2228.45,1233.27 2271.53,1276.34 2349.34,1276.34 2488.6,1415.6 v2(2488.6,1466.56) 2657.86,1466.56 v2(2710.63,1413.79)
  Bottom Layer w8.7: v2(2488.6,1466.56) 2498.56,1456.6 R12.2@2498.56,1418.15 2512.87,1418.15 2519.18,1424.47 U28.24@2519.18,1475.05 ; v2(2710.63,1413.79) 2751.87,1413.77 2775.09,1436.99 U28.14@2775.09,1475.05
MUX_CTRL_LIN_UARTB: R253.1 S4.5 U24.7 U24.8 | length 3427.4
  Top Layer w10.8: U24.8@623.69,3087.46 623.69,3127.27 634.79,3138.37 ; U24.7@643.38,3087.46 643.38,3129.78 634.79,3138.37 ; v2(698.52,3151.47) 678.97,3171.01 R253.1@655.04,3171.01 655.04,3158.63 634.79,3138.37 ; S4.5@1302.05,696.11 v2(1302.02,747.83)
  L3_SIG1 w6: v2(1262.13,3114.05) 1262.13,2669.17 1350.04,2581.26 1350.04,2475.2 1323.45,2448.61 1273.39,2448.61 1244.92,2420.14 1244.92,2391.49 1293.89,2342.51 1293.89,2185.83 1293.42,2185.35 1293.42,2038.85 1252.87,1998.3 1252.87,1669.8 1227.27,1644.2 1227.27,1400.69 1265.06,1362.9 1265.06,1195.36 1310.04,1150.38 1310.04,991.05 1276.15,957.16 1276.15,775.77 1302.02,749.9 v2(1302.02,747.83)
  L6_SIG2 w6: v2(698.52,3151.47) 712.5,3165.45 759.99,3165.45 768.48,3156.96 1219.22,3156.96 v2(1262.13,3114.05)
MUX_CTRL_SPIB_I2C_SYS_RST_HOST_CLK_REQ: R271.1 S4.6 U30.15 | length 3656.1
  Top Layer w7: 340.85,3012.15 355.67,3026.97 U30.15@384.62,3026.97
  Top Layer w10.8: v2(288.35,2963.63) 297.44,2972.73 329.29,2972.73 340.85,2984.29 340.85,3012.15 ; S4.6@1352.05,696.11 1357.39,690.76 v2(1386.8,690.76)
  L3_SIG1 w6: v2(288.35,2963.63) 378.45,2873.53 378.45,1398.43 349.03,1369.01 349.03,657.89 391.49,615.44 473.86,615.44 v2(505.76,647.34)
  L6_SIG2 w6: v2(505.76,647.34) 527.14,625.95 842.08,625.95 858.6,642.47 994.75,642.47 1019.81,617.41 1155.4,617.41 1228.75,690.76 v2(1386.8,690.76)
MUX_CTRL_UARTA_CAN_FD: R128.1 S1.4 U18.8 | length 1840.5
  Top Layer w10.8: v2(373.82,3467.44) 373.82,3545.31 396.89,3568.38 S1.4@396.89,3639.18 ; U18.8@1300.04,2541.56 1300.04,2504.05 1306.31,2497.78 R128.1@1306.31,2480.4 1320.46,2480.4 1323.95,2483.9 v2(1325.9,2483.9)
  L3_SIG1 w6: v2(373.82,3467.44) 406.44,3500.06 498.96,3500.06 535.43,3463.58 647.64,3463.58 888.26,3222.97 888.26,2989.9 1182.82,2695.34 1182.82,2607.55 1306.47,2483.9 v2(1325.9,2483.9)
MUX_CTRL_XDS_DCA_JTAG: R5.1 S4.4 U4.15 | length 2125.6
  Top Layer w7: U4.15@1461.61,1874.02 1461.61,1858.26 1470.17,1849.71
  Top Layer w10.8: S4.4@1252.05,696.11 1252.05,663.12 1271.29,643.88 1386.35,643.88 1455.23,712.76 v2(1455.23,771.97) ; v2(1468.59,1826.95) 1480.87,1826.95 1487.66,1833.75 1483.22,1838.19 1479.83,1838.19 1470.17,1847.85 1470.17,1849.71
  L3_SIG1 w6: v2(1455.23,771.97) 1568.56,771.97 1713.37,916.78 1713.37,962.98 1664.44,1011.91 1573.4,1011.91 1524.82,1060.49 1524.82,1085.47 1453.86,1156.44 1453.86,1295.32 1517.32,1358.78 1517.32,1493.51 1500.41,1510.42 1455.79,1510.42 1401.95,1564.25 1401.95,1676.65 1412.53,1687.22 1412.53,1782.63 1434.11,1804.22 1434.11,1844.36 1478.54,1888.78 1512.24,1888.78 1522.55,1878.47 1522.55,1857.55 1491.95,1826.95 v2(1468.59,1826.95)
MUX_CTRL_XDS_DCA_LP_FTDI_UARTA: R8.1 S1.5 U12.8 | length 1831.1
  Top Layer w10.8: v2(332.77,3439.89) 346.89,3454.01 S1.5@346.89,3639.18 ; R8.1@940.58,2346.78 946.46,2352.65 946.46,2438.67 v2(945.37,2439.76)
  L3_SIG1 w6: v2(332.77,3439.89) 356.59,3416.07 399.33,3416.07 415.73,3432.46 415.73,3467.13 429.84,3481.24 476.43,3481.24 509.84,3447.84 637.8,3447.84 847.59,3238.04 847.59,2974.06 919.54,2902.1 919.54,2552.21 967.32,2504.43 967.32,2461.03 946.05,2439.76 v2(945.37,2439.76)
MUX_CTRL_XDS_FTDI_DCA_LP_RS232: R127.1 S1.2 U18.16 | length 1294.6
  Top Layer w10.8: S1.2@496.89,3639.18 496.89,3499.18 543.1,3452.97 634.62,3452.97 669.57,3487.93 750.24,3487.93 959.66,3278.52 959.66,3119.06 1120.73,2957.99 R127.1@1120.73,2832.5 1120.73,2774.02 U18.16@1120.91,2773.84
NetC37_2: C37.2 R69.1 U5.3 | length 120
  Top Layer w15: U5.3@570.72,2081.85 C37.2@640.72,2081.85 R69.1@690.72,2081.85
NetC39_2: C39.2 R68.1 R79.2 | length 378
  Top Layer w10.8: v2@266.37,2154.18 274.18,2146.37 R79.2@274.18,2121.22 ; R68.1@274.18,1992.48 C39.2@274.18,1947.48 294.13,1947.48 v2@307.98,1933.64
  L3_SIG1 w6: v2(266.66,2154.18) 243.11,2130.63 243.11,1998.8 v2(308.27,1933.64)
NetC43_1: C43.1 D2.1 L1.1
NetC68_1: C68.1 U14.11 | length 76.8
  Top Layer w7: 2233.17,674.96 U14.11@2233.17,719.79
  Top Layer w10.8: 2233.17,674.96 2250.06,658.07 C68.1@2250.06,650.03
NetC69_1: C69.1 U15.7 | length 86.6
  Top Layer w10.8: C69.1@1554.51,1304.85 1554.51,1319.17 1570.99,1335.64 1587.6,1335.64 1603.67,1351.71 U15.7@1613.32,1351.71
NetC94_1: C94.1 R169.1 U21.96 | length 111.9
  Bottom Layer w7: U21.96@1591.66,1695.23 1625.87,1695.23 1639.64,1681.45
  Bottom Layer w8.7: 1639.64,1681.45 C94.1@1639.64,1658.28 R169.1@1674.64,1658.28
NetC95_2: C95.2 R202.2 U21.68 | length 134.3
  Bottom Layer w6: U21.68@1591.66,2136.17 1639.83,2136.17
  Bottom Layer w8.7: 1639.83,2136.17 1652.16,2148.5 1656.1,2148.5 1663.56,2155.96 C95.2@1663.56,2159.9 1680.78,2159.9 1694.35,2146.32 R202.2@1708.21,2146.32
NetC97_2: C97.2 U21.89 Y2.3 | length 154.3
  Bottom Layer w6: 1633.56,1805.46 1635.22,1803.81
  Bottom Layer w7: U21.89@1591.66,1805.46 1633.56,1805.46
  Bottom Layer w8.7: 1635.22,1803.81 1646.78,1792.25 1680.15,1792.25 C97.2@1681.09,1791.31 1713.08,1791.31 1729.37,1775.02 Y2.3@1729.37,1771.08
NetC98_2: C98.2 U21.88 Y2.1 | length 257.5
  Bottom Layer w6: 1623.42,1821.21 1623.73,1820.91 ; 1637.48,1820.91 1637.78,1821.21
  Bottom Layer w7: U21.88@1591.66,1821.21 1623.42,1821.21 ; 1623.73,1820.91 1637.48,1820.91 ; 1637.78,1821.21 1650.7,1821.21
  Bottom Layer w8.7: 1650.7,1821.21 1662.63,1833.14 C98.2@1681.09,1833.14 1681.09,1831.17 1693.89,1818.37 1788.63,1818.37 1800.24,1829.98 Y2.1@1800.24,1861.63
NetC99_2: C99.2 C102.2 R233.1 U21.9 U22.1 | length 571.2
  Bottom Layer w7: U21.9@985.36,1821.21 1015.42,1821.21 1021.58,1815.05 1021.99,1815.05 1026.09,1810.95
  Bottom Layer w8.7: C102.2@876.99,1537.45 C99.2@876.99,1492.45 947.11,1492.45 979.9,1525.23 U22.1@999.51,1525.23 999.51,1550 1020.6,1571.09 R233.1@1054.11,1571.09 1053.44,1571.77 1053.44,1588.61 1048.34,1593.71 1038.79,1593.71 1026.09,1606.41 1026.09,1810.95
NetC110_2: C110.2 R129.1 U19.3 | length 120
  Top Layer w15: U19.3@570.55,1670.14 C110.2@640.55,1670.14 R129.1@690.55,1670.14
NetC111_2: C111.2 R130.1 R140.2 | length 332.6
  Top Layer w10.8: v2(243.99,1728.05) 243.99,1727.19 261.67,1709.51 R140.2@274.01,1709.51 ; R130.1@274.01,1580.77 C111.2@274.01,1535.77 292.8,1535.77 v2(301.87,1544.84)
  L3_SIG1 w6: v2(243.99,1728.05) 242.94,1727 242.94,1587.09 285.19,1544.84 v2(301.87,1544.84)
NetC112_2: C112.2 P1.2 U20.5 | length 136.2
  Top Layer w16: P1.2@272.13,2254.41 372.09,2254.41 U20.5@408.31,2254.41
NetC158_1: C158.1 R259.1 U29.6
NetD1_2: D1.2 L9.2
NetD3_1: D3.1 Q2.3 | length 40
  Top Layer w10.8: Q2.3@1557.5,894.47 D3.1@1557.5,934.47
NetD3_2: D3.2 R172.1 | length 50
  Top Layer w10.8: D3.2@1614.59,934.47 R172.1@1614.59,984.47
NetD4_1: D4.1 R87.2 | length 60.6
  Top Layer w10.8: D4.1@1327.03,1148.5 1386.59,1148.5 R87.2@1387.33,1147.76
NetD5_1: D5.1 Q1.3 | length 30
  Top Layer w10.8: D5.1@1344.53,600.82 Q1.3@1374.53,600.82
NetD5_2: D5.2 R141.1 | length 40
  Top Layer w10.8: R141.1@1247.44,600.82 D5.2@1287.44,600.82
NetD6_2: D6.2 R174.2 | length 50.8
  Top Layer w8: D6.2@1835.31,491.47 D6.2@1835.63,491.14
  Top Layer w12: D6.2@1835.31,491.47 R174.2@1835.31,541.76
NetD7_1: D7.1 Q4.3 | length 30
  Top Layer w10.8: D7.1@1005.84,439.55 Q4.3@1035.84,439.55
NetD7_2: D7.2 R28.1 | length 95.7
  Top Layer w10.8: D7.2@948.75,439.55 948.75,412.6 956.6,404.75 981.86,404.75 988.19,398.43 R28.1@988.19,375
NetD8_1: D8.1 R21.2 | length 143
  Top Layer w15: v2(293.31,905.58) 305.31,917.58 R21.2@305.31,934.5
  Bottom Layer w15: D8.1@264.75,808.26 264.75,877.01 v2(293.31,905.58)
NetD9_2: D9.2 R64.1 | length 35
  Top Layer w10.8: D9.2@483.11,2729.64 R64.1@518.11,2729.64
NetD10_2: D10.2 R252.2 | length 204.2
  Top Layer w10.8: D10.2@1595.8,1033.48 v2(1625.44,1033.48)
  L3_SIG1 w6: v2(1528.95,1124.43) 1549.07,1124.43 1625.44,1048.06 v2(1625.44,1033.48)
  Bottom Layer w8.7: v2(1528.95,1124.43) 1539.29,1114.09 R252.2@1539.29,1096.88
NetD11_1: D11.1 Q3.3 | length 38.1
  Top Layer w10.8: Q3.3@2107.12,436.62 2107.12,474.24 D11.1@2107.28,474.41
  Top Layer w15: Q3.3@2107.12,436.62 Q3.3@2107.28,436.79
NetD11_2: D11.2 R258.1 | length 30
  Top Layer w12: R258.1@2020.2,474.41 D11.2@2050.2,474.41
NetD12_2: D12.2 L8.2
NetD13_2: D13.2 R287.1 | length 50
  Top Layer w10.8: R287.1@646.83,884.63 D13.2@696.83,884.63
NetJ6_4: J6.4 R34.1 | length 96.3
  Bottom Layer w8.7: R34.1@1955.79,270.03 1971.08,270.03 1986.07,285.02 J6.4@1986.07,344.85
NetJ6_5: J6.5 R37.2 | length 201.4
  Bottom Layer w8.7: R37.2@1912.63,733.28 1912.63,718.31 2005.76,625.18 J6.5@2005.76,570.44
NetJ6_6: J6.6 R38.1 | length 145.6
  Bottom Layer w8.7: R38.1@1955.18,235.06 1980.61,235.06 1989.51,243.97 1989.51,259.94 2005.76,276.19 J6.6@2005.76,344.85
NetJ6_7: J6.7 R39.2 | length 193.3
  Bottom Layer w8.7: R39.2@1949.84,732.4 1949.84,709.71 2025.44,634.1 J6.7@2025.44,570.44
NetJ6_8: J6.8 R40.1 | length 85
  Bottom Layer w8.7: R40.1@2025.44,259.85 J6.8@2025.44,344.85
NetJ6_9: J6.9 R41.2 | length 186.2
  Bottom Layer w8.7: R41.2@1986.6,732.4 1986.6,701.31 2045.13,642.78 J6.9@2045.13,570.44
NetJ6_10: J6.10 R42.1 | length 145.6
  Bottom Layer w8.7: J6.10@2045.13,344.85 2045.13,276.19 2061.37,259.94 2061.37,243.97 2070.28,235.06 R42.1@2095.7,235.06
NetJ6_11: J6.11 R52.2 | length 180.3
  Bottom Layer w8.7: R52.2@2021.6,732.84 2021.6,693.42 2064.81,650.21 J6.11@2064.81,570.44
NetJ6_12: J6.12 R53.1 | length 95.8
  Bottom Layer w8.7: J6.12@2064.81,344.85 2064.81,285.9 2080.68,270.03 R53.1@2095.1,270.03
NetJ6_13: J6.13 R58.2 | length 183.7
  Bottom Layer w8.7: R58.2@2055.7,731.31 2074.32,731.31 2084.5,721.13 J6.13@2084.5,570.44
NetJ6_26: J6.26 R219.1 | length 72.7
  Bottom Layer w5.9: R219.1@2197.61,278.42 2198.1,278.42 2207.31,287.62 2207.31,300.96 2202.61,305.66 J6.26@2202.61,344.85
NetJ6_28: J6.28 R220.1 | length 72.9
  Bottom Layer w5.9: J6.28@2222.29,344.85 2222.29,305.66 2217.11,300.47 2217.11,287.62 2226.31,278.42 R220.1@2226.8,278.42
NetJ6_44: J6.44 R225.1 | length 150.4
  Bottom Layer w5.9: R225.1@2350.74,257.17 2350.74,256.68 2360.19,247.23 2379.06,247.23 2384.72,252.88 2384.72,265.25 2381.26,268.7 2376.19,268.7 2372.73,272.16 2372.73,279.03 2376.19,282.48 2380.91,282.48 2384.72,286.29 2384.72,300.72 2379.77,305.66 J6.44@2379.77,344.85
NetJ6_46: J6.46 R226.1 | length 151
  Bottom Layer w5.9: R226.1@2350.74,227.48 2350.74,227.98 2360.19,237.43 2383.12,237.43 2394.52,248.82 2394.52,300.72 2399.46,305.66 J6.46@2399.46,344.85
NetJ6_50: J6.50 R227.1 | length 72.9
  Bottom Layer w5.9: R227.1@2433.83,278.42 2434.32,278.42 2443.77,287.87 2443.77,300.72 2438.83,305.66 J6.50@2438.83,344.85
NetJ6_51: J6.51 R59.2 | length 206.2
  Bottom Layer w8.7: J6.51@2458.51,570.44 R59.2@2458.51,776.68
NetJ6_52: J6.52 R228.1 | length 72.9
  Bottom Layer w5.9: J6.52@2458.51,344.85 2458.51,305.66 2453.57,300.72 2453.57,287.87 2463.02,278.42 R228.1@2463.51,278.42
NetJ6_53: J6.53 R60.2 | length 212.4
  Bottom Layer w8.7: J6.53@2478.2,570.44 2478.2,732.14 2493.18,747.12 R60.2@2493.18,776.68
NetJ6_55: J6.55 R61.2 R152.1 | length 255.6
  Bottom Layer w8.7: J6.55@2497.88,570.44 2497.88,715.4 2532.48,750 R61.2@2532.48,780.02 2563.48,780.02 R152.1@2563.98,780.51
NetJ6_56: J6.56 R229.1 | length 151
  Bottom Layer w5.9: J6.56@2497.88,344.85 2497.88,305.66 2502.83,300.72 2502.83,248.82 2514.22,237.43 2537.15,237.43 2546.6,227.98 R229.1@2546.6,227.48
NetJ6_57: J6.57 R62.2 R153.1 | length 171.3
  Bottom Layer w8.7: J6.57@2517.57,570.44 2517.57,633.86 2540.21,656.5 2555.12,656.5 2561.82,663.2 R62.2@2561.82,682.07 R153.1@2594.47,682.07
NetJ6_58: J6.58 R230.1 | length 150.4
  Bottom Layer w5.9: J6.58@2517.57,344.85 2517.57,305.66 2512.63,300.72 2512.63,286.29 2516.44,282.48 2521.15,282.48 2524.61,279.03 2524.61,272.16 2521.15,268.7 2516.08,268.7 2512.63,265.25 2512.63,252.88 2518.28,247.23 2537.15,247.23 2546.6,256.68 R230.1@2546.6,257.17
NetJ6_59: J6.59 R63.2 | length 103.6
  Bottom Layer w8.7: J6.59@2537.25,570.44 2537.25,623.96 2543.81,630.51 R63.2@2584.66,630.51
NetJ11_5: J11.5 R176.2 R180.2 | length 105
  Bottom Layer w8.7: R180.2@289.56,1762.45 R176.2@289.56,1797.45 J11.5@359.56,1797.45
NetJ11_7: J11.7 R178.2 R198.2 | length 105
  Bottom Layer w8.7: R198.2@289.56,1662.45 R178.2@289.56,1697.45 J11.7@359.56,1697.45
NetJ11_9: J11.9 R254.2 | length 291.6
  Top Layer w8.7: R254.2@414.56,1424.73 415.72,1423.56 438.32,1423.56 v2(439.49,1422.4)
  Bottom Layer w8.7: J11.9@359.56,1597.45 431.59,1597.45 443.81,1585.23 443.81,1557.79 425.28,1539.27 425.28,1436.6 v2(439.49,1422.4)
NetJ11_13: J11.13 R210.2 | length 70
  Bottom Layer w8.7: R210.2@289.56,1397.45 J11.13@359.56,1397.45
NetJ11_14: J11.14 R211.1 | length 75
  Bottom Layer w8.7: J11.14@582,1397.45 R211.1@657,1397.45
NetJ11_15: J11.15 R222.2 | length 70
  Bottom Layer w8.7: R222.2@289.56,1297.45 J11.15@359.56,1297.45
NetJ11_17: J11.17 R224.2 | length 79.5
  Bottom Layer w8.7: R224.2@280.05,1197.45 J11.17@359.56,1197.45
NetJ11_18: J11.18 R232.1 | length 70
  Bottom Layer w8.7: J11.18@582,1197.45 R232.1@652,1197.45
NetJ11_19: J11.19 R238.2 | length 80
  Bottom Layer w8.7: R238.2@279.56,1097.45 J11.19@359.56,1097.45
NetJ11_20: J11.20 R240.1 | length 154.7
  Bottom Layer w8.7: R240.1@493.41,1016.29 493.41,1071.7 519.16,1097.45 J11.20@582,1097.45
NetJ12_1: J12.1 R175.2 | length 70
  Bottom Layer w8.7: R175.2@1989.56,1997.45 J12.1@2059.56,1997.45
NetJ12_6: J12.6 R177.1 | length 70
  Bottom Layer w8.7: J12.6@2282,1797.45 R177.1@2352,1797.45
NetJ12_9: J12.9 R182.2 | length 121.6
  Bottom Layer w8.7: R182.2@1978.06,1658.52 1978.06,1658.02 1983.41,1652.67 1983.91,1652.67 1992.29,1644.29 2037.49,1644.29 2059.56,1622.23 J12.9@2059.56,1597.45
NetJ12_10: J12.10 R183.1 | length 70
  Bottom Layer w8.7: J12.10@2282,1597.45 R183.1@2352,1597.45
NetJ12_12: J12.12 R201.1 | length 70
  Bottom Layer w8.7: J12.12@2282,1497.45 R201.1@2352,1497.45
NetJ12_13: J12.13 R212.2 | length 70
  Bottom Layer w8.7: R212.2@1989.56,1397.45 J12.13@2059.56,1397.45
NetJ12_14: J12.14 R221.1 | length 70
  Bottom Layer w8.7: J12.14@2282,1397.45 R221.1@2352,1397.45
NetJ12_16: J12.16 R223.1 | length 70
  Bottom Layer w8.7: J12.16@2282,1297.45 R223.1@2352,1297.45
NetJ14_3: J14.3 R285.1 | length 632.4
  Top Layer w10.8: J14.3@164.17,2965.75 136.69,2993.23 118.6,2993.23 99.55,2974.18 99.55,2942.19 121.63,2920.11 205.6,2920.11 227.82,2897.89 227.82,2795.94 241.75,2782.02 315.98,2782.02 327.76,2793.79 327.76,2899.67 345.51,2917.43 R285.1@371.87,2917.43
NetJ14_6: J14.6 R286.1 | length 70
  Top Layer w10.8: J14.6@164.17,3265.75 R286.1@234.17,3265.75
NetQ1_1: Q1.1 R171.1 | length 30
  Top Layer w10.8: R171.1@1419.8,555.07 Q1.1@1419.8,585.07
NetQ2_1: Q2.1 R179.2 | length 30
  Top Layer w10.8: R179.2@1531.91,789.67 Q2.1@1531.91,819.67
NetQ3_1: Q3.1 R263.1 | length 30
  Top Layer w10.8: R263.1@2091.37,361.35 Q3.1@2091.37,391.35
NetQ4_1: Q4.1 R66.1 | length 30
  Top Layer w10.8: Q4.1@1081.12,423.81 R66.1@1111.12,423.81
NetR2_1: R2.1 R101.2 U6.2 | length 141.9
  Bottom Layer w8.7: R101.2@986.83,3372.97 R2.1@986.83,3412.97 1042.93,3412.97 1050.78,3420.82 U6.2@1050.78,3455.55
NetR6_2: R6.2 U4.13 | length 85.7
  Top Layer w7: 1416.83,1850.39 1430.12,1863.68 U4.13@1430.12,1874.02
  Top Layer w10.8: R6.2@1360.24,1850.39 1416.83,1850.39
NetR13_2: R13.2 R203.2 S7.2 | length 301.7
  Top Layer w10.8: R203.2@170.45,422.47 S7.2@230.45,422.47 230.45,593.08 256.57,619.2 R13.2@256.57,653.31
NetR14_1: R14.1 R103.2 U6.1 | length 110
  Bottom Layer w8.7: R103.2@991.09,3525.55 R14.1@1031.09,3525.55 U6.1@1031.09,3455.55
NetR16_2: R16.2 R206.2 S8.2 | length 232.8
  Top Layer w10.8: S8.2@597.9,422.1 R16.2@790.69,422.1 ; R16.2@790.97,422.39 R206.2@790.97,462.39
NetR18_2: R18.2 U23.1 | length 71.7
  Top Layer w10.8: U23.1@419.13,785.14 445.72,785.14 456.19,774.67 R18.2@456.19,744.34
NetR19_2: R19.2 U23.4 | length 40
  Top Layer w10.8: U23.4@419.13,861.92 R19.2@459.13,861.92
NetR25_1: R25.1 U6.5 | length 82.9
  Bottom Layer w8.7: U6.5@1109.83,3455.55 1109.83,3414.49 1120.92,3403.4 R25.1@1147.04,3403.4
NetR29_1: R29.1 U6.4 | length 76.6
  Bottom Layer w8.7: U6.4@1090.15,3455.55 1090.15,3491.67 1106.66,3508.18 R29.1@1106.66,3525.29
NetR33_2: R33.2 U14.10 | length 66
  Top Layer w7: 2205.06,685.21 2213.49,693.63 U14.10@2213.49,719.79
  Top Layer w10.8: R33.2@2205.06,657.27 2205.06,685.21
NetR45_1: R45.1 U2.5 | length 60
  Bottom Layer w8.7: U2.5@2903.3,2102.59 R45.1@2963.3,2102.59
NetR46_2: R46.2 U2.2 | length 62.6
  Bottom Layer w8.7: R46.2@2630.32,1993.38 2659.72,1993.38 2668.93,2002.59 U2.2@2689.15,2002.59
NetR47_2: R47.2 U2.3 | length 60
  Bottom Layer w8.7: R47.2@2629.93,2052.59 U2.3@2689.93,2052.59
NetR48_1: R48.1 U2.6 | length 60
  Bottom Layer w8: U2.6@2903.3,2052.59 R48.1@2963.3,2052.59
NetR51_1: R51.1 U2.7 | length 60
  Bottom Layer w8.7: U2.7@2902.52,2002.59 R51.1@2962.52,2002.59
NetR55_1: R55.1 U3.8 | length 41.8
  Top Layer w9: 2792.96,1778.17 U3.8@2807.96,1778.17
  Top Layer w10.8: R55.1@2770.66,1767.34 2782.12,1767.34 2792.96,1778.17
NetR56_1: R56.1 U3.7 | length 42.4
  Top Layer w7: 2784.15,1797.86 U3.7@2807.96,1797.86
  Top Layer w10.8: R56.1@2770.06,1807.94 2770.06,1807.45 2774.01,1803.49 2778.51,1803.49 2784.15,1797.86
NetR70_1: R70.1 S4.12 | length 50
  Top Layer w15: S4.12@1102.05,996.11 R70.1@1102.05,1046.11
NetR72_2: R72.2 U9.1 | length 114.6
  Top Layer w10.8: v2(2841.11,291.81) 2850.01,282.9 U9.1@2872.69,282.9
  Bottom Layer w8.7: v2(2841.11,291.81) 2841.11,326.34 2851.39,336.63 R72.2@2881.63,336.63
NetR76_2: R76.2 R83.1 R84.2 | length 124.6
  Top Layer w10.8: R83.1@1740.44,1576.9 1740.44,1631.21 R76.2@1737.64,1634.01 1740.1,1631.55 R84.2@1802.95,1631.55
NetR78_2: R78.2 U5.1 | length 124.5
  Top Layer w10.8: R78.2@486.8,1929.49 486.8,1961.69 506.96,1981.85 U5.1@570.72,1981.85
NetR80_2: R80.2 U5.4 | length 50
  Top Layer w10.8: U5.4@570.72,2131.85 R80.2@620.72,2131.85
NetR82_1: R82.1 R86.2 U20.3 | length 85
  Top Layer w10.8: U20.3@510.67,2329.21 R86.2@555.67,2329.21 R82.1@555.67,2369.21
NetR94_2: R94.2 U6.3 | length 70
  Bottom Layer w8.7: U6.3@1070.46,3455.55 R94.2@1070.46,3525.55
NetR104_1: R104.1 R113.2 U7.2 | length 141.9
  Bottom Layer w8.7: R104.1@852.43,2811.18 R113.2@852.43,2851.18 908.52,2851.18 916.37,2859.03 U7.2@916.37,2893.76
NetR105_1: R105.1 R114.2 U7.1 | length 110
  Bottom Layer w8.7: R114.2@856.69,2963.76 884.08,2963.76 R105.1@896.69,2963.76 U7.1@896.69,2893.76
NetR106_1: R106.1 R116.2 U8.2 | length 141.9
  Top Layer w10.8: U8.2@2234.29,1952.5 2234.29,1917.77 2242.14,1909.92 R106.1@2298.24,1909.92 R116.2@2298.24,1869.92
NetR107_1: R107.1 R117.2 U8.1 | length 110
  Top Layer w10.8: U8.1@2253.97,1952.5 R107.1@2253.97,2022.5 R117.2@2293.97,2022.5
NetR108_1: R108.1 U7.5 | length 82.9
  Bottom Layer w8.7: U7.5@975.43,2893.76 975.43,2852.7 986.51,2841.61 R108.1@1012.63,2841.61
NetR109_1: R109.1 U8.5 | length 82.9
  Top Layer w10.8: R109.1@2138.03,1900.35 2164.15,1900.35 2175.23,1911.43 U8.5@2175.23,1952.5
NetR110_1: R110.1 U7.4 | length 76.6
  Bottom Layer w8.7: U7.4@955.74,2893.76 955.74,2929.88 972.26,2946.39 R110.1@972.26,2963.5
NetR111_1: R111.1 U8.4 | length 76.6
  Top Layer w10.8: R111.1@2178.41,2022.24 2178.41,2005.13 2194.92,1988.61 U8.4@2194.92,1952.5
NetR112_2: R112.2 U7.3 | length 70
  Bottom Layer w8.7: U7.3@936.06,2893.76 R112.2@936.06,2963.76
NetR115_2: R115.2 U8.3 | length 70
  Top Layer w10.8: U8.3@2214.6,1952.5 R115.2@2214.6,2022.5
NetR122_1: R122.1 U21.35 | length 99.9
  Bottom Layer w6: 1075.03,2273.57 1075.87,2272.73 U21.35@1075.91,2242.47
  Bottom Layer w7: 1061.8,2286.65 1074.88,2273.57
  Bottom Layer w8.7: R122.1@1035.35,2325.03 1042.81,2317.57 1042.81,2304.49 1060.65,2286.65 1061.8,2286.65
NetR124_1: R124.1 U21.36 | length 85.2
  Bottom Layer w6: 1085.33,2294.65 1085.33,2284.76 1090.57,2279.52 1090.57,2272.77 1091.66,2271.68 U21.36@1091.66,2242.47
  Bottom Layer w8.7: 1085.33,2294.65 R124.1@1085.33,2325.03
NetR125_1: R125.1 U21.38 | length 70
  Bottom Layer w6: U21.38@1123.56,2242.87 1123.51,2242.92 1123.51,2267.78 1123.56,2267.82 1123.56,2273.49 1125.7,2275.63
  Bottom Layer w8.7: 1125.7,2275.63 1125.55,2275.78 1135.31,2285.53 R125.1@1135.31,2307.8
NetR126_1: R126.1 U21.40 | length 101.7
  Bottom Layer w6: U21.40@1154.65,2242.47 1154.65,2275.8
  Bottom Layer w8.7: 1154.65,2275.8 1190.47,2311.62 R126.1@1208.2,2311.62
NetR132_2: R132.2 U19.1 | length 124.5
  Top Layer w10.8: R132.2@486.64,1517.78 486.64,1549.98 506.79,1570.14 U19.1@570.55,1570.14
NetR135_1: R135.1 R148.2 U25.2 | length 141.9
  Top Layer w10.8: U25.2@2563.14,1782.25 2563.14,1747.53 2570.99,1739.68 R148.2@2627.09,1739.68 R135.1@2627.09,1699.68
NetR136_1: R136.1 R150.2 U25.1 | length 110
  Top Layer w10.8: U25.1@2582.83,1782.25 R136.1@2582.83,1852.25 R150.2@2622.83,1852.25
NetR137_1: R137.1 U25.5 | length 82.9
  Top Layer w10.8: R137.1@2466.88,1730.11 2493,1730.11 2504.09,1741.19 U25.5@2504.09,1782.25
NetR139_1: R139.1 U25.4 | length 76.6
  Top Layer w10.8: R139.1@2507.26,1851.99 2507.26,1834.88 2523.77,1818.37 U25.4@2523.77,1782.25
NetR142_2: R142.2 U25.3 | length 70
  Top Layer w10.8: U25.3@2543.46,1782.25 R142.2@2543.46,1852.25
NetR143_2: R143.2 U19.4 | length 50
  Top Layer w10.8: U19.4@570.55,1720.14 R143.2@620.55,1720.14
NetR151_2: R151.2 U3.6 | length 61
  Top Layer w8: R151.2@2757.43,1842.82 2769.18,1842.82 U3.6@2794.46,1817.54
  Top Layer w9: U3.6@2794.46,1817.54 U3.6@2807.96,1817.54
NetR159_1: R159.1 U11.6 | length 50
  Top Layer w10.8: R159.1@325.62,2568.79 U11.6@375.62,2568.79
NetR160_1: R160.1 U11.5 | length 50.7
  Top Layer w10.8: R160.1@325.13,2618.33 375.16,2618.33 U11.5@375.62,2618.79
NetR170_1: R170.1 U21.95 | length 90.3
  Bottom Layer w7: U21.95@1591.66,1710.97 1647.09,1710.97
  Bottom Layer w8.7: 1647.09,1710.97 1657.28,1700.79 1676.16,1700.79 R170.1@1677.27,1701.9
NetR181_2: R181.2 U21.33 | length 97.5
  Bottom Layer w6: 1041.14,2275 1044.41,2271.73 U21.33@1044.41,2242.47
  Bottom Layer w8.7: R181.2@994.75,2299.8 994.75,2287.95 1001.21,2281.5 1034.64,2281.5 1041.14,2275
